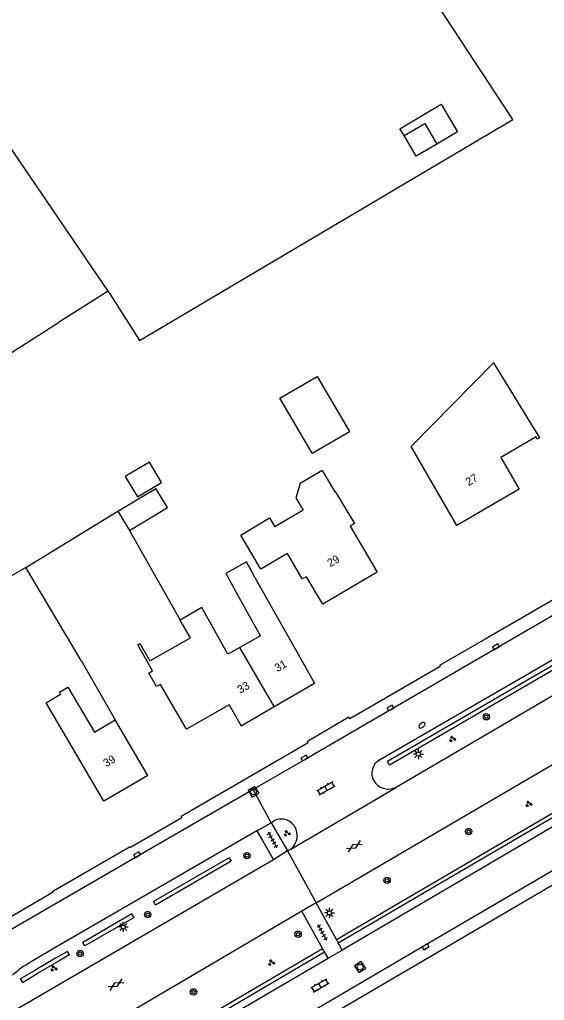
# Model space of a CAD drawing. Extents: x 135999 to 138000, y 396000 to 398501.
# Drawn here: x 136547.8 to 136613.3, y 397709.1 to 397831.7 of the extents above; entities that cross this region are included whole.
import ezdxf

# ---------------------------------------------------------------- set-up
doc = ezdxf.new("R2010")
doc.units = 0
for name, color, linetype in [('gg-afsc-erfafscheiding', 7, 'Continuous'), ('gg-afsc-muur', 7, 'Continuous'), ('gg-anno-huisnummerreeks BGT', 7, 'Continuous'), ('gg-bbg-bijgebouw', 7, 'Continuous'), ('gg-bbg-gedigitaliseerde bebouwing', 7, 'Continuous'), ('gg-bbg-gedigitaliseerde bijgebouw', 7, 'Continuous'), ('gg-bbg-hoofdgebouw', 7, 'Continuous'), ('gg-bbg-luifel en loopbrug', 7, 'Continuous'), ('gg-bbg-tussenscheiding', 7, 'Continuous'), ('gg-knt-verharding', 7, 'Continuous'), ('gt-grn-groengrens', 7, 'Continuous'), ('gt-grn-vlakafsluiter', 7, 'Continuous'), ('gt-grn-weggrens', 7, 'Continuous'), ('gt-symb-boom', 7, 'Continuous'), ('gt-symb-brandkraan', 7, 'Continuous'), ('gt-symb-gesloten verharding', 7, 'Continuous'), ('gt-symb-groenvak', 7, 'Continuous'), ('gt-symb-klinker verharding', 7, 'Continuous'), ('gt-symb-kolk', 7, 'Continuous'), ('gt-symb-lichtmast', 7, 'Continuous'), ('gt-symb-rioolschacht', 7, 'Continuous'), ('gt-symb-tegel verharding', 7, 'Continuous'), ('gx-grn-maaiveld', 7, 'Continuous')]:
    doc.layers.add(name, color=color, linetype=linetype)

# ---------------------------------------------------------------- blocks, each defined once
blk = doc.blocks.new('gt0-RS')
at = {"layer": 'gt-symb-rioolschacht'}
blk.add_lwpolyline([(-0.5, -0.5), (0.5, -0.5), (0.5, 0.5), (-0.5, 0.5)], close=True, dxfattribs=at)
blk.add_circle((0, 0), 0.375, dxfattribs=at)
blk = doc.blocks.new('gt0-TEG1')
at = {"layer": 'gt-symb-tegel verharding'}
for p, q in [((-1.12, 0), (1.13, 0)), ((-0.9, -0.25), (-0.9, 0.25)), ((-0.45, -0.25), (-0.45, 0.25)), ((0, -0.25), (0, 0.25)), ((0.45, -0.25), (0.45, 0.25)), ((0.9, -0.25), (0.9, 0.25))]:
    blk.add_line(p, q, dxfattribs=at)
blk = doc.blocks.new('gt0-GRVAK')
at = {"layer": 'gt-symb-groenvak'}
for p, q in [((-0.11, 0.19), (-0.23, 0.24)), ((-0.18, 0.15), (0.09, 0.15)), ((-0.09, 0.21), (-0.16, 0.32)), ((-0.05, 0.21), (-0.05, 0.39)), ((0, 0.21), (0.06, 0.32)), ((0.02, 0.19), (0.13, 0.24)), ((0.26, -0.05), (0.2, 0.06)), ((0.3, -0.05), (0.3, 0.13)), ((0.35, -0.05), (0.41, 0.06)), ((-0.24, -0.23), (-0.36, -0.18)), ((-0.32, -0.26), (-0.05, -0.26)), ((-0.23, -0.21), (-0.29, -0.1)), ((-0.18, -0.2), (-0.18, -0.02)), ((-0.14, -0.21), (-0.07, -0.1)), ((-0.12, -0.23), (0, -0.18)), ((0.24, -0.07), (0.12, -0.02)), ((0.17, -0.11), (0.44, -0.11)), ((0.37, -0.07), (0.49, -0.02))]:
    blk.add_line(p, q, dxfattribs=at)
blk = doc.blocks.new('gt0-KOLK')
at = {"layer": 'gt-symb-kolk'}
blk.add_lwpolyline([(0, 0), (0.38, 0), (0.38, 0.4), (-0.38, 0.4), (-0.38, 0), (0, 0)], dxfattribs=at)
blk = doc.blocks.new('gt0-KL1')
at = {"layer": 'gt-symb-klinker verharding'}
for p, q in [((-1.15, 0.3), (1.15, 0.3)), ((-1, -0.3), (-1, 0.3)), ((-0.5, 0.3), (-0.5, 0.45)), ((0, -0.3), (0, 0.3)), ((0.5, 0.3), (0.5, 0.45)), ((1, -0.3), (1, 0.3)), ((-1.15, -0.3), (1.15, -0.3)), ((-0.5, -0.45), (-0.5, -0.3)), ((0.5, -0.45), (0.5, -0.3))]:
    blk.add_line(p, q, dxfattribs=at)
blk = doc.blocks.new('gt0-BOOM')
at = {"layer": 'gt-symb-boom'}
for radius in [0.4, 0.2]:
    blk.add_circle((0, 0), radius, dxfattribs=at)
blk = doc.blocks.new('gt0-GESVH1')
at = {"layer": 'gt-symb-gesloten verharding'}
for p, q in [((-0.99, -0.26), (0.01, 0.24)), ((0.01, -0.26), (-0.99, 0.24)), ((0.01, 0.24), (1.01, -0.26)), ((1.01, 0.24), (0.01, -0.26))]:
    blk.add_line(p, q, dxfattribs=at)
blk = doc.blocks.new('gt0-LMAST')
at = {"layer": 'gt-symb-lichtmast'}
for p, q in [((-0.18, 0.17), (-0.45, 0.44)), ((-0.01, 0.25), (-0.01, 0.62)), ((0.17, 0.17), (0.44, 0.44)), ((-0.26, 0), (-0.63, 0)), ((-0.18, -0.18), (-0.45, -0.45)), ((-0.01, -0.25), (-0.01, -0.63)), ((0.44, -0.45), (0.17, -0.18)), ((0.24, 0), (0.62, 0))]:
    blk.add_line(p, q, dxfattribs=at)
blk.add_circle((-0.01, 0), 0.25, dxfattribs=at)
blk = doc.blocks.new('gt0-BR')
at = {"layer": 'gt-symb-brandkraan'}
for centre, radius, start, end in [((-0.24, 0), 0.206, 107.5669, 252.4331), ((0.6, -2.66), 3, 106.892, 107.5669), ((0, -0.69), 0.938, 73.108, 106.892), ((-0.6, -2.66), 3, 72.4331, 73.108), ((0.24, 0), 0.206, 287.567, 72.4331), ((0.6, 2.66), 3, 252.4331, 253.108), ((0, 0.69), 0.938, 253.108, 286.8921), ((-0.6, 2.66), 3, 286.8921, 287.567)]:
    blk.add_arc(centre, radius, start, end, dxfattribs=at)

msp = doc.modelspace()

# ---------------------------------------------------------------- linework, layer by layer
at = {"layer": 'gg-afsc-erfafscheiding'}
for p, q in [((136548.54, 397763.19), (136559.41, 397769.86)), ((136559.41, 397769.86), (136560.03, 397770.24)), ((136561.47, 397767.84), (136567.25, 397757.66)), ((136567.25, 397757.66), (136567.82, 397756.64)), ((136555.44, 397751.56), (136559.71, 397744.15))]:
    msp.add_line(p, q, dxfattribs=at)
at = {"layer": 'gg-afsc-muur'}
for p, q in [((136548.54, 397763.19), (136544.57, 397760.93)), ((136555.44, 397751.56), (136548.54, 397763.19)), ((136588.89, 397744.48), (136583.73, 397741.45)), ((136588.89, 397744.48), (136583.73, 397741.45))]:
    msp.add_line(p, q, dxfattribs=at)
at = {"layer": 'gg-bbg-bijgebouw'}
for p, q in [((136584.28, 397777.48), (136588.95, 397780.19)), ((136560.03, 397770.24), (136561.47, 397767.84))]:
    msp.add_line(p, q, dxfattribs=at)
at = {"layer": 'gg-bbg-gedigitaliseerde bebouwing'}
for p, q in [((136577.16, 397761.94), (136584.59, 397748.76)), ((136577.85, 397754.65), (136574.59, 397760.51)), ((136577.85, 397754.65), (136575.25, 397753.2))]:
    msp.add_line(p, q, dxfattribs=at)
for points in [[(136602.38, 397768.46), (136596.65, 397778.31), (136606.95, 397788.79), (136612.68, 397779.4)], [(136585.54, 397775.32), (136582.8, 397773.68), (136582.28, 397771.91), (136583.18, 397770.37), (136579.64, 397768.3)], [(136577.91, 397762.98), (136575.38, 397767.24), (136578.99, 397769.39), (136579.64, 397768.3)], [(136577.16, 397761.94), (136576.08, 397763.89), (136573.51, 397762.46), (136574.59, 397760.51)], [(136575.25, 397753.2), (136573.75, 397752.37), (136570.52, 397758.19), (136567.82, 397756.64)], [(136562.52, 397753.53), (136562.79, 397753.69), (136564.04, 397751.52), (136569.1, 397754.42), (136567.82, 397756.64)]]:
    msp.add_lwpolyline(points, dxfattribs=at)
at = {"layer": 'gg-bbg-gedigitaliseerde bijgebouw'}
msp.add_line((136560.03, 397770.24), (136564.79, 397773.09), dxfattribs=at)
for points in [[(136595.77, 397817.16), (136598.35, 397818.69), (136599.88, 397816.11)], [(136599.88, 397816.11), (136597.3, 397814.58), (136595.77, 397817.16)], [(136584.28, 397777.48), (136580.28, 397784.36), (136584.93, 397787.08), (136588.95, 397780.19)], [(136562.48, 397772.02), (136565.5, 397773.82), (136563.98, 397776.36), (136560.96, 397774.55), (136562.48, 397772.02)], [(136561.47, 397767.84), (136566.23, 397770.68), (136564.79, 397773.09)]]:
    msp.add_lwpolyline(points, dxfattribs=at)
at = {"layer": 'gg-bbg-hoofdgebouw'}
for p, q in [((136579.54, 397745.82), (136584.59, 397748.76)), ((136563.77, 397737.22), (136559.71, 397744.15)), ((136563.77, 397737.22), (136558.27, 397734.01))]:
    msp.add_line(p, q, dxfattribs=at)
for points in [[(136612.68, 397779.4), (136612.41, 397779.25), (136612.26, 397779.51), (136607.87, 397776.94), (136610.16, 397773), (136602.38, 397768.46)], [(136585.54, 397775.32), (136587.12, 397772.67), (136587.19, 397772.71), (136589.57, 397768.69), (136589.05, 397768.38), (136592.42, 397762.6)], [(136592.42, 397762.6), (136585.62, 397758.61), (136583.59, 397762.05), (136583.07, 397761.77), (136581.21, 397764.93), (136577.91, 397762.98)], [(136573.92, 397746.05), (136568.61, 397742.98), (136565.36, 397748.6), (136564.88, 397748.33), (136563.9, 397750.01), (136564.37, 397750.29), (136562.52, 397753.53)], [(136558.27, 397734.01), (136551.08, 397746.3), (136552.89, 397747.36), (136552.74, 397747.62), (136553.8, 397748.24), (136557.1, 397742.62), (136559.71, 397744.15)], [(136573.92, 397746.05), (136575.43, 397743.43), (136579.54, 397745.82)]]:
    msp.add_lwpolyline(points, dxfattribs=at)
at = {"layer": 'gg-bbg-luifel en loopbrug'}
msp.add_lwpolyline([(136595.77, 397817.16), (136595.26, 397818.02), (136600.42, 397821.08), (136602.46, 397817.64), (136599.88, 397816.11)], dxfattribs=at)
at = {"layer": 'gg-bbg-tussenscheiding'}
msp.add_line((136579.54, 397745.82), (136575.25, 397753.2), dxfattribs=at)
at = {"layer": 'gg-knt-verharding'}
for p, q in [((136682.32, 397786.98), (136594.69, 397735.69)), ((136581.64, 397728.01), (136594.69, 397735.69)), ((136620.94, 397734.67), (136588.06, 397715.4)), ((136577.4, 397730.28), (136579.2, 397731.31)), ((136579.2, 397731.31), (136579.47, 397731.49)), ((136579.2, 397731.31), (136581.24, 397727.78)), ((136577.4, 397730.28), (136578.1, 397729.08)), ((136578.1, 397729.08), (136579.49, 397726.69)), ((136581.24, 397727.78), (136579.49, 397726.69)), ((136581.64, 397728.01), (136581.24, 397727.78)), ((136584.81, 397721.3), (136583, 397720.28)), ((136585.61, 397715.6), (136583, 397720.28)), ((136587.32, 397716.74), (136584.81, 397721.3)), ((136587.56, 397716.3), (136587.32, 397716.74)), ((136585.85, 397715.16), (136585.61, 397715.6)), ((136586.29, 397714.37), (136588.06, 397715.4)), ((136587.68, 397716.09), (136587.56, 397716.3)), ((136588.06, 397715.4), (136587.68, 397716.09)), ((136586.29, 397714.37), (136585.85, 397715.16))]:
    msp.add_line(p, q, dxfattribs=at)
for points in [[(136584.81, 397721.3), (136694.7, 397785.67), (136748.36, 397817)], [(136639.62, 397771.79), (136639.08, 397771.51), (136633.2, 397768.13), (136621.58, 397761.39), (136609.28, 397754.23), (136594.17, 397745.47), (136583.43, 397739.22), (136576.92, 397735.46)], [(136592.71, 397739.17), (136640.97, 397767.11), (136642.89, 397768.09), (136644.6, 397768.88), (136646.76, 397769.93), (136647.89, 397770.54)], [(136631.89, 397769.25), (136631.93, 397769.17), (136621.9, 397763.37), (136621.82, 397763.47), (136605.89, 397754.24), (136600.2, 397750.95), (136600.28, 397750.83), (136589, 397744.29), (136588.89, 397744.48)], [(136539.91, 397715.62), (136551.96, 397722.69), (136551.92, 397722.76), (136561.58, 397728.33), (136561.63, 397728.25), (136568.04, 397731.96), (136567.92, 397732.15), (136583.8, 397741.33), (136583.73, 397741.45)], [(136576.92, 397735.46), (136562.52, 397727.13), (136547.38, 397718.34), (136538.92, 397713.43), (136534, 397710.38), (136533.62, 397710.16)], [(136623.33, 397730.58), (136615.23, 397725.85), (136598.37, 397715.98), (136582.05, 397706.4), (136527.15, 397674.25), (136512.93, 397665.97), (136476.34, 397644.56), (136460.4, 397635.27), (136457.49, 397633.57)], [(136626.04, 397730.38), (136581.85, 397704.48), (136513.35, 397664.37), (136513.27, 397664.51)], [(136577.4, 397730.28), (136551.67, 397715.37), (136549.22, 397713.94)], [(136579.49, 397726.69), (136481.87, 397669.84), (136412.85, 397629.52)], [(136583, 397720.28), (136541.99, 397696.14), (136519.43, 397682.97)], [(136455.1, 397637.63), (136490.66, 397658.44), (136522.15, 397676.85), (136586.29, 397714.37)]]:
    msp.add_lwpolyline(points, dxfattribs=at)
for centre, radius, start, end in [((136593.67, 397737.5), 1.92, 119.9831, 209.3279), ((136593.84, 397737.67), 2.15, 210.8661, 293.2373), ((136580.47, 397729.86), 1.91, 30.9786, 121.5316), ((136580.25, 397729.7), 2.19, 309.6622, 31.4986), ((136556.01, 397701.86), 13.85, 119.3409, 131.1943)]:
    msp.add_arc(centre, radius, start, end, dxfattribs=at)
at = {"layer": 'gt-grn-groengrens'}
for p, q in [((136573.92, 397726.93), (136564.49, 397721.47)), ((136522.23, 397678.53), (136585.61, 397715.6)), ((136522.48, 397678.09), (136585.85, 397715.16)), ((136547.85, 397711.79), (136549.8, 397712.94))]:
    msp.add_line(p, q, dxfattribs=at)
for points in [[(136587.32, 397716.74), (136689.01, 397776.28), (136711.34, 397789.87), (136723.02, 397798.65), (136749.67, 397814.36)], [(136587.56, 397716.3), (136689.27, 397775.85), (136711.62, 397789.45), (136723.3, 397798.24), (136749.93, 397813.93), (136749.67, 397814.36)], [(136673.21, 397784.6), (136593.97, 397738.52), (136593.72, 397738.96)], [(136662.66, 397779.1), (136662.68, 397779.06), (136593.72, 397738.96)], [(136573.92, 397726.93), (136574.17, 397726.5), (136564.74, 397721.03), (136564.49, 397721.47)], [(136562.06, 397719.48), (136561.8, 397719.91), (136555.68, 397716.36)], [(136562.06, 397719.48), (136555.93, 397715.93), (136555.68, 397716.36)], [(136553.99, 397714.8), (136553.74, 397715.24), (136552.25, 397714.38), (136549.8, 397712.94)], [(136553.99, 397714.8), (136552.5, 397713.94), (136550.05, 397712.51)], [(136547.85, 397711.79), (136548.11, 397711.35), (136550.05, 397712.51)]]:
    msp.add_lwpolyline(points, dxfattribs=at)
at = {"layer": 'gt-grn-vlakafsluiter'}
msp.add_line((136558.84, 397797.71), (136552.61, 397793.8), dxfattribs=at)
msp.add_lwpolyline([(136558.84, 397797.71), (136562.73, 397791.55), (136609.37, 397819.16), (136595.35, 397840.59), (136642.02, 397872.49)], dxfattribs=at)
at = {"layer": 'gt-grn-weggrens'}
for p, q in [((136579.2, 397731.31), (136576.92, 397735.46)), ((136581.24, 397727.78), (136584.81, 397721.3))]:
    msp.add_line(p, q, dxfattribs=at)
at = {"layer": 'gx-grn-maaiveld'}
for p, q in [((136558.84, 397797.71), (136498.12, 397886.85)), ((136504.69, 397763.39), (136552.61, 397793.8))]:
    msp.add_line(p, q, dxfattribs=at)

# ---------------------------------------------------------------- block references
at = {"layer": 'gt-symb-boom'}
for p in [(136606.05, 397744.55), (136603.84, 397730.21), (136576.16, 397727.19), (136593.66, 397724.11), (136563.76, 397719.83), (136582.54, 397717.38), (136555.32, 397714.96), (136569.48, 397710.17)]:
    msp.add_blockref('gt0-BOOM', p, dxfattribs=at)
at = {"layer": 'gt-symb-brandkraan', "rotation": -142.10993718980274}
msp.add_blockref('gt0-BR', (136598.01, 397743.49), dxfattribs=at)
at = {"layer": 'gt-symb-gesloten verharding'}
for p, rotation in [((136589.58, 397728.35), -149.79306598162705), ((136559.81, 397711.07), -149.99927221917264)]:
    msp.add_blockref('gt0-GESVH1', p, dxfattribs=dict(at, rotation=rotation))
at = {"layer": 'gt-symb-groenvak'}
for p in [(136601.81, 397741.77), (136611.34, 397733.65), (136581.15, 397729.98), (136579.2, 397713.82), (136552.02, 397713.1)]:
    msp.add_blockref('gt0-GRVAK', p, dxfattribs=at)
at = {"layer": 'gt-symb-klinker verharding'}
for p, rotation in [((136586.03, 397735.61), 29.794617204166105), ((136585.29, 397710.98), 29.951082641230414)]:
    msp.add_blockref('gt0-KL1', p, dxfattribs=dict(at, rotation=rotation))
at = {"layer": 'gt-symb-kolk'}
for p, rotation in [((136607.35, 397753.11), 30.128600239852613), ((136594.17, 397745.47), 30.079025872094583), ((136583.43, 397739.22), 30.206934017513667), ((136562.52, 397727.13), 30.050323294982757), ((136598.37, 397715.98), -149.586769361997)]:
    msp.add_blockref('gt0-KOLK', p, dxfattribs=dict(at, rotation=rotation))
at = {"layer": 'gt-symb-lichtmast'}
for p in [(136597.57, 397739.89), (136586.46, 397720.05), (136560.71, 397718.3)]:
    msp.add_blockref('gt0-LMAST', p, dxfattribs=at)
at = {"layer": 'gt-symb-rioolschacht'}
for p, rotation in [((136576.98, 397735.17), 30.66892664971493), ((136590.29, 397713.28), -146.96171538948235)]:
    msp.add_blockref('gt0-RS', p, dxfattribs=dict(at, rotation=rotation))
at = {"layer": 'gt-symb-tegel verharding', "rotation": -61.256964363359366}
for p in [(136579.34, 397729.18), (136585.56, 397717.63)]:
    msp.add_blockref('gt0-TEG1', p, dxfattribs=at)

# ---------------------------------------------------------------- texts
at = {"layer": 'gg-anno-huisnummerreeks BGT'}
for s, rotation, p in [('27', 30.3, (136603.82, 397773.35)), ('29', 30.4, (136586.55, 397763.22)), ('31', 30.2, (136579.97, 397750.12)), ('33', 30.2, (136575.3, 397747.41)), ('39', 30.3, (136558.57, 397738.23))]:
    msp.add_text(s, height=1, rotation=rotation, dxfattribs=at).set_placement(p)

doc.saveas('drawing.dxf')
